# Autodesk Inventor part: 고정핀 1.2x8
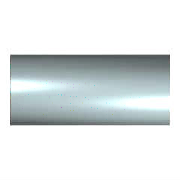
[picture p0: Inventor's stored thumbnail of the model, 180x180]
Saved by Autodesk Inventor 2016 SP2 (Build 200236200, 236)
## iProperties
IsCustomPart: 1
Created: 2012-02
Part Number: 고정핀 1.2x8
Material: 강철, 연강
Description: 평행 핀
Document SubType Name: Modeling
Standard: KS B 1320
Designer: P15F
Standards Organization: KS
Language: ko-KR
Size Designation: C 1.2 x  8
Categories: <MemberInstance><Categories><Category DisplayName="조임쇠" InternalName="e4da775c-781d-43d5-af7c-5136215cf5a6" Mnemonic="FSTN"><Category DisplayName="핀" InternalNa
Density: 1 g/cm^3
Appearance: 노란색
Author: P15F
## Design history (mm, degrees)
sketch "스케치1"
  geometry: C1 r 0.6 at (0, 0); 1 further point
  constraints: 1 centre point, 1 coincident
  dimensions: "d1" = 1.2 diameter of C1 (= NND)
extrude "본체" new body sketch "스케치1" distance "d2" = 8 (= NLG); taper "d3" = 0 deg
node "작업 평면1"
body "Solid1"
other parameters: "NND" = 1.2 [user parameter; used in 1 equation term], "NLG" = 8 [user parameter; used in 1 equation term], "d8" = 0, "d9" = 0, "d10" = 0
